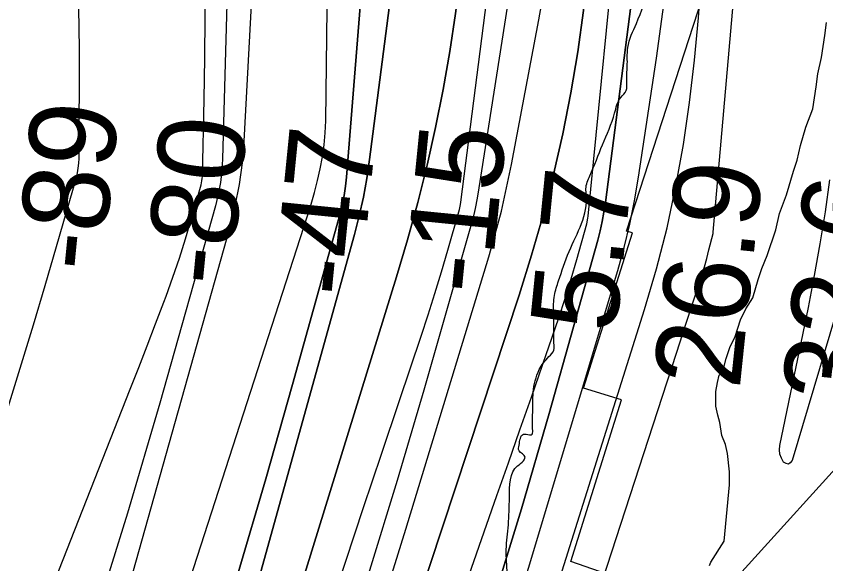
# Model space of a CAD drawing. Extents: x 3329297 to 3367176, y 649250 to 674653.
# Drawn here: x 3342260 to 3342886, y 662858 to 663281 of the extents above; entities that cross this region are included whole.
import ezdxf

# ---------------------------------------------------------------- set-up
doc = ezdxf.new("R2010")
doc.units = 0
for name, color, linetype in [('V-RIVR-EDGE', 7, 'Continuous'), ('V-RIVR-RANG', 7, 'Continuous'), ('V-RRAP-RVMT', 7, 'Continuous'), ('V-SITE-VEGE', 7, 'Continuous'), ('V-TOPO-DPTH', 7, 'Continuous'), ('V-TOPO-MAJR', 7, 'Continuous'), ('V-TOPO-MINR', 7, 'Continuous'), ('V-TOPO-WATR', 7, 'Continuous'), ('V-WETL-SWMP', 7, 'Continuous')]:
    doc.layers.add(name, color=color, linetype=linetype)

msp = doc.modelspace()

# ---------------------------------------------------------------- linework, layer by layer
at = {"layer": 'V-RIVR-EDGE'}
msp.add_spline([(3340543.49, 660085.6), (3340562.91, 660098.74), (3340575.72, 660104.14), (3340585.05, 660109.54), (3340589.7, 660111.08), (3340590.86, 660109.14), (3340597.81, 660094.39), (3340601.29, 660093.99), (3340606.34, 660095.14), (3340606.73, 660097.08), (3340606.35, 660100.96), (3340599.79, 660112.22), (3340596.7, 660118.04), (3340597.48, 660121.14), (3340599.82, 660124.24), (3340602.92, 660125.78), (3340609.53, 660130.03), (3340610.7, 660133.13), (3340611.1, 660138.95), (3340614.21, 660141.66), (3340620.42, 660143.58), (3340627.02, 660148.22), (3340632.85, 660152.86), (3340639.85, 660158.27), (3340647.22, 660161.74), (3340655.76, 660164.43), (3340667.02, 660168.28), (3340677.11, 660172.14), (3340684.48, 660174.83), (3340692.65, 660181.79), (3340699.25, 660187.21), (3340702.75, 660189.14), (3340709.35, 660193), (3340717.5, 660197.63), (3340731.88, 660207.29), (3340748.19, 660216.56), (3340768.38, 660227.76), (3340779.25, 660232.38), (3340792.46, 660240.88), (3340805.67, 660251.71), (3340823.92, 660262.91), (3340832.07, 660265.6), (3340837.9, 660270.63), (3340847.24, 660280.69), (3340854.23, 660286.49), (3340861.21, 660286.47), (3340868.98, 660289.94), (3340876.75, 660296.13), (3340884.91, 660303.86), (3340891.52, 660310.44), (3340896.97, 660318.18), (3340903.58, 660325.15), (3340904.37, 660330.19), (3340904.76, 660334.45), (3340908.65, 660337.16), (3340912.53, 660339.47), (3340913.71, 660343.74), (3340916.83, 660351.87), (3340921.89, 660359.23), (3340933.17, 660372.77), (3340942.5, 660382.83), (3340944.45, 660389.03), (3340947.56, 660392.13), (3340951.45, 660394.45), (3340956.11, 660398.7), (3340965.45, 660409.54), (3340972.05, 660415.72), (3340980.21, 660421.13), (3340987.99, 660430.42), (3340991.89, 660439.33), (3340994.62, 660445.92), (3341001.24, 660456.76), (3341008.24, 660462.56), (3341019.5, 660469.12), (3341022.61, 660474.16), (3341027.28, 660478.02), (3341033.1, 660482.28), (3341044.37, 660491.55), (3341056.81, 660501.22), (3341062.25, 660506.25), (3341064.2, 660512.45), (3341069.26, 660518.25), (3341074.7, 660522.12), (3341079.75, 660525.21), (3341087.91, 660533.33), (3341094.52, 660540.29), (3341099.98, 660551.14), (3341101.93, 660558.5), (3341101.95, 660564.32), (3341101.95, 660566.26), (3341105.83, 660567.8), (3341107.39, 660570.9), (3341108.19, 660579.43), (3341109.36, 660581.36), (3341111.69, 660582.52), (3341116.35, 660584.06), (3341119.07, 660586.38), (3341131.9, 660599.92), (3341130.74, 660602.25), (3341129.58, 660604.58), (3341130.37, 660609.23), (3341131.15, 660611.56), (3341134.26, 660614.27), (3341139.7, 660619.29), (3341147.47, 660623.93), (3341155.25, 660632.44), (3341160.31, 660640.18), (3341161.87, 660646), (3341164.59, 660647.15), (3341171.96, 660648.3), (3341176.63, 660653.33), (3341185.57, 660661.45), (3341197.22, 660669.95), (3341202.65, 660670.72), (3341208.87, 660674.58), (3341212.76, 660681.16), (3341218.98, 660685.8), (3341223.63, 660686.56), (3341228.3, 660690.82), (3341239.56, 660696.61), (3341242.27, 660696.99), (3341247.7, 660695.04), (3341251.97, 660695.8), (3341254.69, 660699.67), (3341257.81, 660706.26), (3341265.19, 660713.61), (3341272.18, 660717.47), (3341278.78, 660719.39), (3341285.77, 660723.64), (3341288.11, 660727.12), (3341288.89, 660730.61), (3341291.61, 660733.32), (3341297.45, 660739.51), (3341303.67, 660745.31), (3341316.48, 660753.04), (3341337.85, 660770.05), (3341347.56, 660774.29), (3341351.82, 660771.95), (3341356.47, 660772.33), (3341359.2, 660775.81), (3341357.66, 660783.57), (3341359.22, 660785.51), (3341364.27, 660789.37), (3341367.76, 660789.75), (3341372.8, 660786.64), (3341377.44, 660784.3), (3341380.16, 660785.07), (3341385.21, 660787.38), (3341385.99, 660789.71), (3341386.78, 660796.68), (3341388.73, 660799.01), (3341390.67, 660800.94), (3341401.93, 660807.89), (3341425.62, 660820.63), (3341448.15, 660836.48), (3341459.42, 660845.76), (3341473.4, 660853.48), (3341492.82, 660866.23), (3341509.52, 660875.88), (3341528.94, 660885.92), (3341568.15, 660904.05), (3341576.69, 660906.74), (3341582.52, 660911.38), (3341589.12, 660916.4), (3341596.89, 660921.81), (3341605.05, 660926.06), (3341608.93, 660926.82), (3341613.19, 660926.43), (3341626, 660930.66), (3341639.2, 660936.45), (3341658.23, 660946.87), (3341680.75, 660960), (3341702.89, 660972.35), (3341720.75, 660981.23), (3341737.44, 660987), (3341750.26, 660995.89), (3341758.04, 661005.18), (3341780.97, 661024.51), (3341791.86, 661039.61), (3341805.08, 661053.54), (3341819.48, 661072.51), (3341836.2, 661091.08), (3341848.27, 661110.83), (3341856.83, 661123.6), (3341870.06, 661139.86), (3341888.33, 661157.26), (3341900, 661173.14), (3341908.96, 661187.46), (3341921.81, 661209.92), (3341929.99, 661226.19), (3341939.34, 661242.84), (3341942.06, 661244.78), (3341943.22, 661244), (3341944.75, 661235.85), (3341949.41, 661235.84), (3341954.45, 661237.76), (3341956.01, 661241.64), (3341951.37, 661243.98), (3341950.6, 661247.08), (3341951, 661251.35), (3341952.96, 661259.87), (3341955.7, 661272.28), (3341958.46, 661290.5), (3341960.82, 661303.29), (3341965.13, 661320.73), (3341976.06, 661348.62), (3341983.49, 661373.81), (3341990.92, 661399), (3341994.85, 661420.71), (3341995.66, 661433.89), (3341998.38, 661436.99), (3342001.09, 661436.2), (3342003.81, 661438.52), (3342004.21, 661443.95), (3342004.24, 661455.97), (3342002.71, 661461.41), (3342004.27, 661464.89), (3342009.32, 661471.47), (3342020.6, 661484.24), (3342033.83, 661502.05), (3342040.82, 661507.46), (3342045.88, 661513.27), (3342046.28, 661517.53), (3342044.36, 661524.52), (3342045.91, 661525.68), (3342047.07, 661525.67), (3342052.11, 661523.33), (3342053.28, 661524.49), (3342063.01, 661538.82), (3342071.18, 661551.21), (3342074.69, 661557.79), (3342082.47, 661570.18), (3342088.7, 661576.76), (3342099.58, 661588.37), (3342104.25, 661594.56), (3342110.49, 661608.51), (3342119.84, 661627.1), (3342128.4, 661637.93), (3342135.41, 661647.61), (3342140.08, 661653.81), (3342142.02, 661656.52), (3342148.26, 661668.91), (3342155.64, 661676.65), (3342159.16, 661685.17), (3342161.49, 661688.27), (3342166.54, 661690.97), (3342169.67, 661702.6), (3342177.46, 661716.54), (3342191.47, 661736.28), (3342210.14, 661760.28), (3342224.15, 661779.25), (3342232.33, 661792.41), (3342242.06, 661806.74), (3342247.51, 661815.25), (3342252.98, 661831.14), (3342263.11, 661850.51), (3342268.95, 661858.63), (3342277.12, 661872.96), (3342284.15, 661891.95), (3342293.11, 661908.21), (3342302.46, 661923.7), (3342310.25, 661939.2), (3342314.93, 661948.1), (3342327.38, 661965.91), (3342325.85, 661973.28), (3342327.41, 661977.55), (3342330.91, 661981.42), (3342336.35, 661986.44), (3342339.47, 661993.42), (3342342.6, 662003.88), (3342345.32, 662007.36), (3342350.38, 662013.17), (3342354.66, 662019.36), (3342356.61, 662025.56), (3342357.41, 662034.09), (3342360.53, 662039.12), (3342366.75, 662046.09), (3342373.76, 662059.65), (3342381.55, 662072.81), (3342385.46, 662085.6), (3342390.54, 662099.55), (3342396.37, 662107.29), (3342399.1, 662113.88), (3342402.61, 662121.62), (3342413.53, 662146.8), (3342430.7, 662189.03), (3342442, 662209.94), (3342453.7, 662236.67), (3342465, 662260.3), (3342466.58, 662269.6), (3342471.66, 662285.88), (3342476.34, 662295.95), (3342481, 662300.59), (3342482.95, 662305.24), (3342483.35, 662308.73), (3342487.64, 662319.19), (3342491.54, 662328.88), (3342501.68, 662348.63), (3342505.2, 662360.64), (3342509.11, 662375.76), (3342511.48, 662391.65), (3342513.82, 662399.01), (3342520.44, 662409.08), (3342525.9, 662421.48), (3342528.64, 662432.72), (3342531.41, 662453.26), (3342534.97, 662481.18), (3342536.95, 662497.46), (3342541.25, 662512.18), (3342547.49, 662526.13), (3342556.05, 662537.36), (3342563.04, 662544.32), (3342566.16, 662550.52), (3342570.46, 662564.47), (3342572.44, 662579.97), (3342576.33, 662585.39), (3342582.17, 662592.36), (3342585.68, 662602.43), (3342587.24, 662606.7), (3342589.97, 662610.95), (3342595.04, 662623.74), (3342596.62, 662635.37), (3342599.36, 662643.89), (3342600.14, 662647.38), (3342599.37, 662648.55), (3342596.66, 662651.66), (3342596.67, 662654.76), (3342598.61, 662657.47), (3342603.67, 662661.72), (3342609.9, 662671.79), (3342617.69, 662688.06), (3342629.78, 662713.24), (3342637.58, 662731.06), (3342640.7, 662739.58), (3342640.71, 662745.4), (3342640.35, 662754.7), (3342641.91, 662758.58), (3342645.02, 662761.67), (3342647.74, 662765.16), (3342646.25, 662787.27), (3342646.27, 662798.51), (3342641.69, 662824.89), (3342639.81, 662850.11), (3342639.08, 662868.72), (3342640.68, 662887.72), (3342641.51, 662909.05), (3342647.77, 662933.46), (3342652.44, 662937.33), (3342653.61, 662940.04), (3342648.96, 662945.09), (3342648.97, 662949.36), (3342652.49, 662957.88), (3342654.42, 662957.88), (3342659.08, 662957.87), (3342659.48, 662962.13), (3342659.51, 662974.54), (3342659.93, 662990.05), (3342664.63, 663007.88), (3342672.02, 663017.94), (3342675.92, 663022.98), (3342675.93, 663028.41), (3342675.95, 663036.94), (3342675.6, 663052.06), (3342676.41, 663065.25), (3342679.54, 663076.48), (3342687.74, 663099.34), (3342701.03, 663143.13), (3342700.66, 663147.79), (3342703.78, 663157.86), (3342713.54, 663181.88), (3342722.9, 663206.29), (3342727.59, 663218.3), (3342731.87, 663223.72), (3342732.27, 663230.31), (3342732.69, 663242.72), (3342732.71, 663249.31), (3342733.11, 663257.07), (3342739.75, 663275.67), (3342750.29, 663303.95), (3342759.67, 663332.24), (3342762.03, 663344.25), (3342764.01, 663362.86), (3342765.98, 663374.88), (3342766.38, 663378.37), (3342765.22, 663381.47), (3342765.62, 663384.57), (3342766.79, 663390.78), (3342769.92, 663398.91), (3342771.87, 663405.89), (3342776.95, 663418.29), (3342777.37, 663431.47), (3342779.34, 663445.04), (3342776.67, 663465.6), (3342775.96, 663489.26), (3342776.01, 663509.81), (3342772.92, 663515.25), (3342764.01, 663520.7), (3342756.65, 663521.88), (3342756.27, 663524.98), (3342757.44, 663528.86), (3342761.32, 663530.4), (3342772.57, 663528.82), (3342774.51, 663529.2), (3342775.68, 663532.69), (3342776.86, 663541.22), (3342775.41, 663580.39), (3342775.84, 663596.68), (3342776.26, 663611.41), (3342776.27, 663616.84), (3342776.69, 663627.7), (3342781.37, 663638.55), (3342786.13, 663683.52), (3342792.46, 663731.98), (3342794.87, 663765.71), (3342797.62, 663781.99), (3342805.94, 663853.72), (3342813.86, 663919.24), (3342817.07, 663960.72), (3342819.5, 664002.21), (3342819.94, 664025.87), (3342819.97, 664036.34), (3342818.06, 664048.75), (3342817.71, 664064.26), (3342816.41, 664076.7)], degree=3, dxfattribs=at)
at = {"layer": 'V-RRAP-RVMT'}
for p, q in [((3342732.05, 663114.98), (3342808.02, 663348.84)), ((3342698.8, 662993.58), (3342736.74, 663113.72)), ((3342736.74, 663113.72), (3342732.05, 663114.98)), ((3342728.22, 662984.57), (3342698.8, 662993.58)), ((3342689.07, 662859.46), (3342728.22, 662984.57)), ((3342728.33, 662845.66), (3342689.07, 662859.46))]:
    msp.add_line(p, q, dxfattribs=at)
at = {"layer": 'V-SITE-VEGE'}
msp.add_lwpolyline([(3342796.18, 662856.44), (3342797.39, 662858.93), (3342807.69, 662875.11), (3342811.85, 662918.85), (3342811.73, 662928.76), (3342810.14, 662942.89), (3342808.64, 662949.95), (3342805.73, 662956.99), (3342804.19, 662966.88), (3342802.71, 662972.52), (3342801.21, 662979.58), (3342801.07, 662990.9), (3342802.4, 662997.99), (3342803.75, 663003.67), (3342806.54, 663006.53), (3342809.25, 663016.47), (3342811.98, 663024.99), (3342816.12, 663033.53), (3342820.21, 663046.32), (3342824.35, 663054.86), (3342829.91, 663063.42), (3342833.99, 663077.62), (3342836.71, 663086.14), (3342840.84, 663096.1), (3342847.67, 663115.99), (3342850.35, 663128.76), (3342855.84, 663142.98), (3342861.28, 663161.44), (3342864, 663169.96), (3342866.7, 663181.32), (3342870.77, 663195.52), (3342876.26, 663209.74), (3342878.89, 663226.75), (3342880.18, 663236.67), (3342882.85, 663249.44), (3342885.48, 663266.46), (3342886.78, 663276.38)], dxfattribs=at)
at = {"layer": 'V-TOPO-DPTH'}
for points in [[(3342818.28, 664568.1), (3342772.99, 663696.25), (3342766.9, 663600.27), (3342759.35, 663504.41), (3342749.62, 663408.75), (3342738.42, 663313.23), (3342715.74, 663137.07), (3342714.63, 663129.76), (3342713.32, 663122.48), (3342711.69, 663115.27), (3342709.85, 663108.1), (3342672.3, 662974.03), (3342650.78, 662900.09), (3342628.29, 662826.47), (3342604.31, 662753.31), (3342579.35, 662680.46), (3342534.77, 662554.49), (3342502.9, 662464.39), (3342471.04, 662374.28), (3342439.21, 662284.16)], [(3342110.6, 661866.46), (3342385.98, 662705.93), (3342409.12, 662778.16), (3342431.59, 662850.6), (3342453.05, 662923.34), (3342473.84, 662996.29), (3342510.57, 663128.63), (3342512.29, 663135.6), (3342513.74, 663142.61), (3342514.78, 663149.69), (3342515.56, 663156.83), (3342558.52, 663694.97), (3342569.11, 663835.86), (3342578.82, 663976.8)], [(3342578.82, 663976.8), (3342569.11, 663835.86), (3342558.52, 663694.97), (3342515.56, 663156.83), (3342514.78, 663149.69), (3342513.74, 663142.61), (3342512.29, 663135.6), (3342510.57, 663128.63), (3342473.84, 662996.29), (3342453.05, 662923.34), (3342431.59, 662850.6), (3342409.12, 662778.16), (3342385.98, 662705.93), (3342110.6, 661866.46)], [(3342631.55, 663957.1), (3342616.8, 663833.33), (3342602.86, 663717.86), (3342588.69, 663602.43), (3342574.17, 663487.03), (3342559.41, 663371.67), (3342533.34, 663170.33), (3342531.13, 663155.72), (3342528.51, 663141.2), (3342525.27, 663126.8), (3342521.63, 663112.48), (3342446.33, 662841.34), (3342403.24, 662691.98), (3342358.16, 662543.25), (3342310.1, 662395.45), (3342260.05, 662248.27)], [(3342631.55, 663957.1), (3342616.8, 663833.33), (3342602.86, 663717.86), (3342588.69, 663602.43), (3342574.17, 663487.03), (3342559.41, 663371.67), (3342533.34, 663170.33), (3342531.13, 663155.72), (3342528.51, 663141.2), (3342525.27, 663126.8), (3342521.63, 663112.48), (3342446.33, 662841.34), (3342403.24, 662691.98), (3342358.16, 662543.25), (3342310.1, 662395.45), (3342260.05, 662248.27)], [(3342673.85, 663884.64), (3342667.06, 663828.39), (3342620.11, 663453.32), (3342616.02, 663420.07), (3342612.02, 663386.81), (3342608.16, 663353.53), (3342604.39, 663320.24), (3342603.59, 663313.04), (3342599.84, 663283.42), (3342595.49, 663253.89), (3342590.26, 663224.5), (3342584.43, 663195.21), (3342577.77, 663166.1), (3342570.61, 663137.12), (3342562.68, 663108.33), (3342554.24, 663079.68), (3342354.45, 662432.86), (3342322.65, 662334.64)], [(3342322.65, 662334.64), (3342354.45, 662432.86), (3342554.24, 663079.68), (3342562.68, 663108.33), (3342570.61, 663137.12), (3342577.77, 663166.1), (3342584.43, 663195.21), (3342590.26, 663224.5), (3342595.49, 663253.89), (3342599.84, 663283.42), (3342603.59, 663313.04), (3342604.39, 663320.24), (3342608.16, 663353.53), (3342612.02, 663386.81), (3342616.02, 663420.07), (3342620.11, 663453.32), (3342667.06, 663828.39), (3342673.85, 663884.64)], [(3342352.45, 662314.94), (3342378.41, 662391.49), (3342488.3, 662714.27), (3342511.28, 662783.41), (3342533.59, 662852.76), (3342554.88, 662922.43), (3342575.5, 662992.31), (3342611.26, 663116.82), (3342613.35, 663124.63), (3342615.24, 663132.49), (3342616.84, 663140.42), (3342618.24, 663148.39), (3342661.25, 663423.37), (3342674.16, 663511.09), (3342686, 663598.95), (3342696.25, 663687), (3342705.43, 663775.19), (3342713.14, 663863.53)], [(3342352.45, 662314.94), (3342378.41, 662391.49), (3342488.3, 662714.27), (3342511.28, 662783.41), (3342533.59, 662852.76), (3342554.88, 662922.43), (3342575.5, 662992.31), (3342611.26, 663116.82), (3342613.35, 663124.63), (3342615.24, 663132.49), (3342616.84, 663140.42), (3342618.24, 663148.39), (3342661.25, 663423.37), (3342674.16, 663511.09), (3342686, 663598.95), (3342696.25, 663687), (3342705.43, 663775.19), (3342713.14, 663863.53)], [(3342746.15, 663858.52), (3342738.73, 663737.33), (3342729.48, 663616.26), (3342719.01, 663495.28), (3342702.31, 663317.85), (3342698.72, 663285.73), (3342694.39, 663253.73), (3342688.94, 663221.9), (3342682.75, 663190.19), (3342675.5, 663158.69), (3342667.56, 663127.39), (3342658.6, 663096.35), (3342648.97, 663065.5), (3342540.2, 662736.18), (3342488.49, 662582.32), (3342435.72, 662428.83), (3342381.36, 662275.9)], [(3342381.36, 662275.9), (3342435.72, 662428.83), (3342488.49, 662582.32), (3342540.2, 662736.18), (3342648.97, 663065.5), (3342658.6, 663096.35), (3342667.56, 663127.39), (3342675.5, 663158.69), (3342682.75, 663190.19), (3342688.94, 663221.9), (3342694.39, 663253.73), (3342698.72, 663285.73), (3342702.31, 663317.85), (3342719.01, 663495.28), (3342729.48, 663616.26), (3342738.73, 663737.33), (3342746.15, 663858.52)]]:
    msp.add_lwpolyline(points, dxfattribs=at)
at = {"layer": 'V-TOPO-MAJR'}
for points in [[(3342206.15, 662267.8), (3342232.36, 662344.88), (3342485.27, 663126.95), (3342488.04, 663135.94), (3342490.64, 663144.97), (3342492.99, 663154.08), (3342495.16, 663163.23), (3342496.92, 663172.45), (3342498.3, 663181.72), (3342499.09, 663191.05), (3342499.49, 663200.43), (3342514.84, 664482.04)], [(3342493.27, 662168.07), (3342749.16, 662954.1), (3342756.39, 662976.31), (3342763.62, 662998.52), (3342770.84, 663020.73), (3342778.07, 663042.94), (3342788.32, 663074.46), (3342790.35, 663080.93), (3342792.3, 663087.42), (3342794.12, 663093.95), (3342795.86, 663100.51), (3342799.04, 663113.06), (3342799.17, 663113.66), (3342799.22, 663113.97), (3342799.25, 663114.28), (3342853.37, 663730.49), (3342864.42, 663871.85)]]:
    msp.add_lwpolyline(points, dxfattribs=at)
at = {"layer": 'V-TOPO-MINR'}
for points in [[(3342482.87, 662327.47), (3342528.61, 662458.41), (3342572.98, 662589.8), (3342615.28, 662721.87), (3342656.2, 662854.39), (3342725.32, 663084.61), (3342730.26, 663102.45), (3342734.68, 663120.4), (3342738.33, 663138.53), (3342741.47, 663156.78), (3342755.25, 663248.91), (3342763.98, 663313.41), (3342771.49, 663378.02), (3342777.18, 663442.83), (3342781.67, 663507.75), (3342840.16, 664572.02)], [(3342511.54, 662325.51), (3342558.52, 662464.09), (3342603.81, 662603.26), (3342746.02, 663054.3), (3342755.21, 663085.85), (3342763.44, 663117.63), (3342770.25, 663149.74), (3342776.12, 663182.07), (3342780.78, 663214.63), (3342784.78, 663247.25), (3342787.8, 663279.98), (3342790.17, 663312.79), (3342862.06, 664575.94)], [(3342439.21, 662284.16), (3342471.04, 662374.28), (3342502.9, 662464.39), (3342534.77, 662554.49), (3342579.35, 662680.46), (3342604.31, 662753.31), (3342628.29, 662826.47), (3342650.78, 662900.09), (3342672.3, 662974.03), (3342709.85, 663108.1), (3342711.69, 663115.27), (3342713.32, 663122.48), (3342714.63, 663129.76), (3342715.74, 663137.07), (3342738.42, 663313.23), (3342749.62, 663408.75), (3342759.35, 663504.41), (3342766.9, 663600.27), (3342772.99, 663696.25), (3342818.28, 664568.1)], [(3342403.7, 663154.03), (3342403.89, 663155.64), (3342403.99, 663157.27), (3342405.46, 663217.22), (3342405.99, 663248.83), (3342406.2, 663280.44), (3342405.92, 663312.04), (3342405.32, 663343.65), (3342374.3, 664504.93)], [(3342110.6, 661866.46), (3342385.98, 662705.93), (3342409.12, 662778.16), (3342431.59, 662850.6), (3342453.05, 662923.34), (3342473.84, 662996.29), (3342510.57, 663128.63), (3342512.29, 663135.6), (3342513.74, 663142.61), (3342514.78, 663149.69), (3342515.56, 663156.83), (3342558.52, 663694.97), (3342569.11, 663835.86), (3342578.82, 663976.8)], [(3342435.07, 663969.41), (3342436, 663833.47), (3342434.24, 663697.47), (3342419.64, 663170.97), (3342419.04, 663161.74), (3342417.99, 663152.58), (3342416.26, 663143.52), (3342414.08, 663134.53), (3342371.04, 662981.85), (3342346.02, 662896.9), (3342319.69, 662812.37), (3342291.4, 662728.47), (3342261.81, 662645), (3342200.57, 662478.48), (3342178.01, 662417.33), (3342155.37, 662356.21), (3342132.59, 662295.14)], [(3342260.05, 662248.27), (3342310.1, 662395.45), (3342358.16, 662543.25), (3342403.24, 662691.98), (3342446.33, 662841.34), (3342521.63, 663112.48), (3342525.27, 663126.8), (3342528.51, 663141.2), (3342531.13, 663155.72), (3342533.34, 663170.33), (3342559.41, 663371.67), (3342574.17, 663487.03), (3342588.69, 663602.43), (3342602.86, 663717.86), (3342616.8, 663833.33), (3342631.55, 663957.1)], [(3342473.09, 663891.72), (3342467.26, 663765.45), (3342436.15, 663184.63), (3342434.69, 663167.81), (3342432.49, 663151.11), (3342429.2, 663134.59), (3342425.18, 663118.2), (3342345.28, 662833.79), (3342298.9, 662676.39), (3342249.89, 662519.84), (3342196.93, 662364.58), (3342141.34, 662210.18)], [(3342322.65, 662334.64), (3342354.45, 662432.86), (3342554.24, 663079.68), (3342562.68, 663108.33), (3342570.61, 663137.12), (3342577.77, 663166.1), (3342584.43, 663195.21), (3342590.26, 663224.5), (3342595.49, 663253.89), (3342599.84, 663283.42), (3342603.59, 663313.04), (3342604.39, 663320.24), (3342608.16, 663353.53), (3342612.02, 663386.81), (3342616.02, 663420.07), (3342620.11, 663453.32), (3342667.06, 663828.39), (3342673.85, 663884.64)], [(3342426.15, 662323.63), (3342463.12, 662426.85), (3342631.88, 662910.45), (3342640.74, 662935.83), (3342649.61, 662961.21), (3342658.47, 662986.59), (3342667.34, 663011.97), (3342674.66, 663032.9), (3342679.73, 663047.85), (3342684.61, 663062.87), (3342689.2, 663077.98), (3342693.6, 663093.15), (3342701.3, 663120.64), (3342702.23, 663125.09), (3342702.42, 663126.6), (3342726.99, 663375.03), (3342738.45, 663500.83), (3342748.63, 663626.72), (3342756.89, 663752.76), (3342763.85, 663878.89)], [(3342352.45, 662314.94), (3342378.41, 662391.49), (3342488.3, 662714.27), (3342511.28, 662783.41), (3342533.59, 662852.76), (3342554.88, 662922.43), (3342575.5, 662992.31), (3342611.26, 663116.82), (3342613.35, 663124.63), (3342615.24, 663132.49), (3342616.84, 663140.42), (3342618.24, 663148.39), (3342661.25, 663423.37), (3342674.16, 663511.09), (3342686, 663598.95), (3342696.25, 663687), (3342705.43, 663775.19), (3342713.14, 663863.53)], [(3342204.23, 661826.59), (3342402.09, 662395.78), (3342443.57, 662517.4), (3342484.1, 662639.33), (3342523.21, 662761.72), (3342561.36, 662884.42), (3342625.52, 663095.08), (3342630.59, 663112.76), (3342635.27, 663130.53), (3342639.38, 663148.45), (3342643.1, 663166.46), (3342664.34, 663278.42), (3342677.35, 663352.64), (3342688.97, 663427.05), (3342698.5, 663501.75), (3342706.65, 663576.65), (3342712.22, 663635.5), (3342721.3, 663740.03), (3342729.33, 663844.63)], [(3342299.57, 662206.75), (3342501.21, 662818.25), (3342514.92, 662859.7), (3342528.68, 662901.14), (3342542.52, 662942.54), (3342556.4, 662983.93), (3342573.14, 663033.68), (3342578.58, 663050.22), (3342583.87, 663066.81), (3342588.94, 663083.46), (3342593.86, 663100.16), (3342602.4, 663129.92), (3342602.89, 663131.79), (3342603.67, 663135.57), (3342603.96, 663137.48), (3342666.47, 663626.05), (3342675.33, 663698.09), (3342683.73, 663770.19), (3342691.42, 663842.36)], [(3342308.04, 663163.82), (3342308.41, 663167.48), (3342308.58, 663171.17), (3342308.9, 663256.08), (3342308.47, 663287.43)], [(3341933.68, 661950.78), (3342254.9, 662982.25), (3342264.18, 663012.4), (3342273.33, 663042.59), (3342282.29, 663072.83), (3342291.11, 663103.12), (3342306.5, 663156.61), (3342307.37, 663160.2), (3342308.04, 663163.82)], [(3342906.14, 663091.49), (3342860.18, 662937.44), (3342858.8, 662935.74), (3342857.28, 662934.83), (3342855.53, 662935.13), (3342853.63, 662936.23), (3342851.89, 662939.25), (3342850.73, 662942.4), (3342850.41, 662945.75), (3342850.65, 662949.22), (3342872.78, 663056.03), (3342877.59, 663080.62), (3342882.02, 663105.27), (3342885.9, 663130.01), (3342889.4, 663154.82)], [(3342047.46, 662210.15), (3342097.89, 662346.09), (3342148.93, 662481.79), (3342200.92, 662617.13), (3342253.53, 662752.23), (3342348.14, 662992.77), (3342354.72, 663009.58), (3342361.25, 663026.4), (3342367.73, 663043.25), (3342374.16, 663060.12), (3342375.88, 663064.66), (3342381.22, 663079.33), (3342386.31, 663094.08), (3342391, 663108.97), (3342395.43, 663123.93), (3342403.02, 663150.85), (3342403.7, 663154.03)]]:
    msp.add_lwpolyline(points, dxfattribs=at)
at = {"layer": 'V-TOPO-WATR'}
msp.add_lwpolyline([(3342381.36, 662275.9), (3342435.72, 662428.83), (3342488.49, 662582.32), (3342540.2, 662736.18), (3342648.97, 663065.5), (3342658.6, 663096.35), (3342667.56, 663127.39), (3342675.5, 663158.69), (3342682.75, 663190.19), (3342688.94, 663221.9), (3342694.39, 663253.73), (3342698.72, 663285.73), (3342702.31, 663317.85), (3342719.01, 663495.28), (3342729.48, 663616.26), (3342738.73, 663737.33), (3342746.15, 663858.52)], dxfattribs=at)
at = {"layer": 'V-WETL-SWMP'}
msp.add_lwpolyline([(3342603.84, 662221.67), (3342674.12, 662378.18), (3342740.64, 662495.03), (3342758.45, 662543.36), (3342772.05, 662588.81), (3342782.81, 662635.64), (3342781.14, 662656.84), (3342765.18, 662681.96), (3342768.29, 662685.78), (3342771.68, 662692.78), (3342775.71, 662704.65), (3342781.72, 662725.58), (3342782.25, 662738.8), (3342782.04, 662756.18), (3342778.95, 662781.87), (3342777.31, 662802.02), (3342778.31, 662811.7), (3342818.9, 662848.99), (3342911.08, 662950.58)], dxfattribs=at)

# ---------------------------------------------------------------- texts
at = {"layer": 'V-RIVR-RANG'}
for s, rotation, p in [('-89', 84.31333, (3342326.66, 663082.43)), ('-80', 84.31333, (3342426.04, 663071.23)), ('-47', 84.31333, (3342525.68, 663062.64)), ('-15', 84.31333, (3342626.39, 663064.83)), ('5.7', 84.31333, (3342723.96, 663035.52)), ('26.9', 84.02833, (3342819.52, 662991.92)), ('32.6', 84.02833, (3342918.84, 662980.19))]:
    msp.add_text(s, height=67, rotation=rotation, dxfattribs=at).set_placement(p)

doc.saveas('drawing.dxf')
